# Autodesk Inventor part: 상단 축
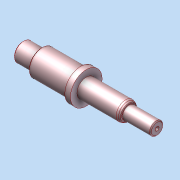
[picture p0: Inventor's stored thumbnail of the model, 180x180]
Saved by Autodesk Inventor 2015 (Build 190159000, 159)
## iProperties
Created: 2024-05
Part Number: 상단 축
Material: 일반
Document SubType Name: Modeling
Designer: Administrator
Density: 1 g/cm^3
Appearance: 기본값
Author: Administrator
Author: jhkim
Creation Date: 2024-05-07
Sending System: Autodesk Inventor 2025
Preprocessor: ST-DEVELOPER v20
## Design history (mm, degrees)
node "상단 축1"
node "솔리드1"
node "기준1"
